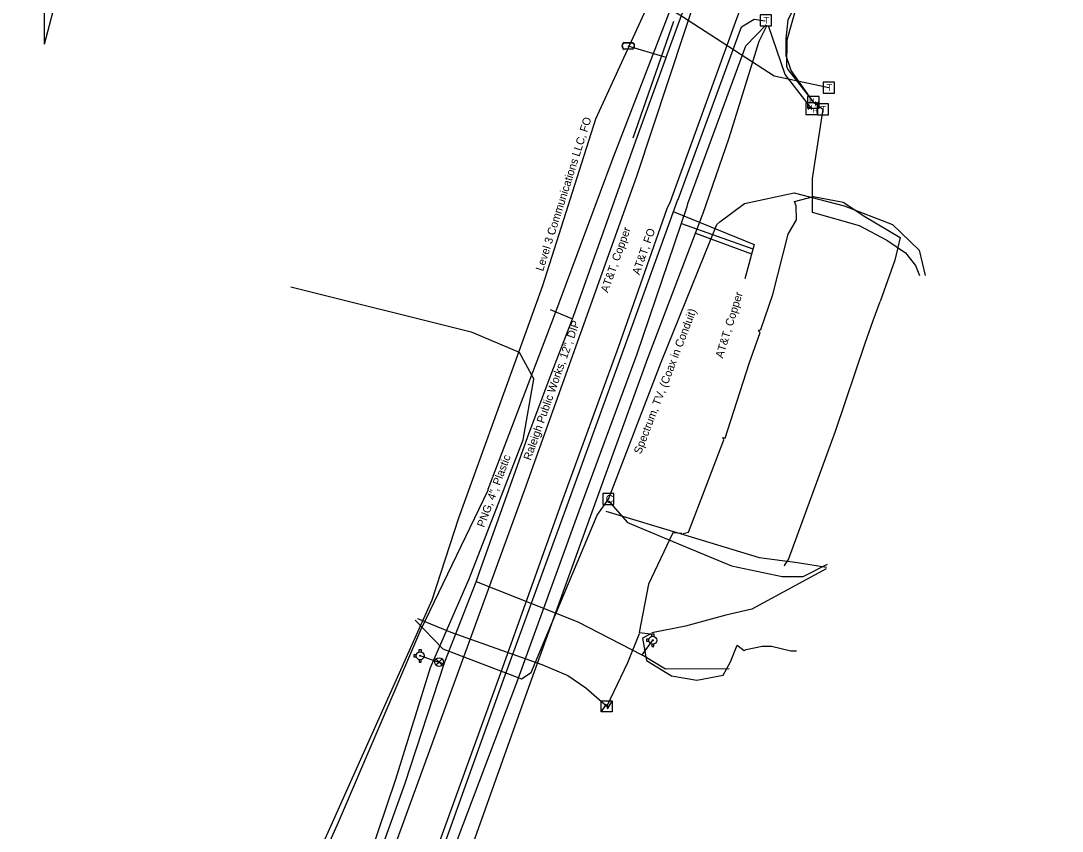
# Model space of a CAD drawing. Extents: x 2070721 to 2083039, y 729290 to 737883.
# Drawn here: x 2080924 to 2081444, y 733253 to 733658 of the extents above; entities that cross this region are included whole.
import ezdxf

# ---------------------------------------------------------------- set-up
doc = ezdxf.new("R2010")
doc.units = 0
for name, color, linetype in [('Cogo Default Point CELL', 7, 'Continuous'), ('COGO Default Point Elevation', 7, 'Continuous'), ('COGO Default Point Number', 7, 'Continuous'), ('Exist Utilities Gas UG Line SUE Cogo Point CELL', 7, 'Continuous'), ('Exist Utilities Gas UG Line SUE LOS B Cogo Comment', 7, 'Continuous'), ('Exist Utilities Gas Valve Cogo Elevation', 7, 'Continuous'), ('Exist Utilities Telephone UG Cable SUE LOS C Cogo Comment', 7, 'Continuous'), ('Exist Utilities Telephone UG Cable SUE LOS C Cogo Number', 7, 'Continuous'), ('Exist Utilities Telephone UG FO Cogo Point CELL', 7, 'Continuous'), ('Exist Utilities Telephone UG FO SUE LOS B Cogo Comment', 7, 'Continuous'), ('Exist Utilities Telephone UG FO SUE LOS B Cogo Number', 7, 'Continuous'), ('Exist Utilities TV Pedestal Cogo Elevation', 7, 'Continuous'), ('Exist Utilities TV Pedestal Cogo Number', 7, 'Continuous'), ('Exist Utilities TV UG Cable Cogo Point CELL', 7, 'Continuous'), ('Exist Utilities TV UG Cable SUE LOS C Cogo Comment', 7, 'Continuous'), ('Exist Utilities TV UG Cable SUE LOS C Cogo Number', 7, 'Continuous'), ('Exist Utilities TV UG Cable SUE LOS C Cogo Point CELL', 7, 'Continuous'), ('Exist Utilities Water Manhole Cogo Number', 7, 'Continuous'), ('Exist Utilities Water Meter Cogo Elevation', 7, 'Continuous'), ('Exist Utilities Water Meter Cogo Number', 7, 'Continuous')]:
    doc.layers.add(name, color=color, linetype=linetype)

msp = doc.modelspace()

# ---------------------------------------------------------------- linework, layer by layer
at = {"layer": 'Cogo Default Point CELL'}
msp.add_line((2081217.67, 733419.02), (2081217.67, 733419.02), dxfattribs=at)
msp.add_lwpolyline([(2081214.9, 733416.24), (2081220.45, 733416.24), (2081220.45, 733421.79), (2081214.9, 733421.79), (2081214.9, 733416.24)], dxfattribs=at)
at = {"layer": 'COGO Default Point Elevation'}
msp.add_lwpolyline([(2081134.76, 733339.06), (2081131.61, 733335.91), (2081133.18, 733337.48), (2081134.76, 733335.91), (2081131.61, 733339.06)], dxfattribs=at)
msp.add_circle((2081133.18, 733337.48), 2.23, dxfattribs=at)
at = {"layer": 'COGO Default Point Number'}
for p, q in [((2081239.93, 733348.42), (2081239.93, 733348.42)), ((2081123.71, 733340.65), (2081123.71, 733340.65))]:
    msp.add_line(p, q, dxfattribs=at)
for points in [[(2081238.01, 733348.93), (2081236.73, 733348.93), (2081236.73, 733347.91), (2081238.01, 733347.91)], [(2081239.41, 733350.33), (2081239.41, 733351.62), (2081240.44, 733351.62), (2081240.44, 733350.31)], [(2081123.2, 733342.57), (2081123.2, 733343.85), (2081124.22, 733343.85), (2081124.22, 733342.54)], [(2081239.41, 733346.51), (2081239.41, 733345.22), (2081240.44, 733345.22), (2081240.44, 733346.53)], [(2081121.8, 733341.17), (2081120.51, 733341.17), (2081120.51, 733340.14), (2081121.8, 733340.14)], [(2081123.2, 733338.74), (2081123.2, 733337.45), (2081124.22, 733337.45), (2081124.22, 733338.77)]]:
    msp.add_lwpolyline(points, dxfattribs=at)
for centre, radius in [((2081239.93, 733348.42), 1.98), ((2081239.93, 733348.42), 0.243), ((2081123.71, 733340.65), 1.98), ((2081123.71, 733340.65), 0.243)]:
    msp.add_circle(centre, radius, dxfattribs=at)
at = {"layer": 'Exist Utilities Gas Valve Cogo Elevation'}
for p, q in [((2081254.27, 733556.72), (2081289.92, 733543.99)), ((2081261.33, 733551.91), (2081289.31, 733541.49))]:
    msp.add_line(p, q, dxfattribs=at)
msp.add_lwpolyline([(2081250.19, 733562.64), (2081290.57, 733546.24), (2081285.89, 733528.96)], dxfattribs=at)
at = {"layer": 'Exist Utilities Telephone UG Cable SUE LOS C Cogo Comment'}
msp.add_line((2081230.17, 733599.51), (2081250.4, 733657.7), dxfattribs=at)
at = {"layer": 'Exist Utilities Telephone UG Cable SUE LOS C Cogo Number'}
msp.add_line((2081216.97, 733315.56), (2081216.97, 733315.56), dxfattribs=at)
msp.add_lwpolyline([(2081214.13, 733318.17), (2081219.68, 733318.17), (2081219.68, 733312.62), (2081214.13, 733312.62)], close=True, dxfattribs=at)
for points in [[(2081214.13, 733312.62), (2081216.77, 733316.56), (2081217.4, 733314.35), (2081219.68, 733318.17)], [(2081214.2, 733312.62), (2081216.77, 733316.35), (2081217.36, 733314.17), (2081219.68, 733318.02)]]:
    msp.add_lwpolyline(points, dxfattribs=at)
at = {"layer": 'Exist Utilities Telephone UG FO Cogo Point CELL'}
msp.add_line((2081227.69, 733645.4), (2081227.69, 733645.4), dxfattribs=at)
for points in [[(2081225.66, 733647.1), (2081229.73, 733647.1)], [(2081225.66, 733646.96), (2081229.73, 733646.96)], [(2081229.73, 733643.83), (2081225.63, 733643.83)], [(2081229.73, 733643.7), (2081225.63, 733643.7)]]:
    msp.add_lwpolyline(points, dxfattribs=at)
for centre, radius, start, end in [((2081226.39, 733645.39), 1.86, 113.178, 245.9794), ((2081226.4, 733645.39), 1.73, 115.3009, 243.7824), ((2081228.99, 733645.4), 1.86, 293.6483, 66.3084), ((2081229, 733645.4), 1.73, 295.1272, 64.8728)]:
    msp.add_arc(centre, radius, start, end, dxfattribs=at)
at = {"layer": 'Exist Utilities Telephone UG FO SUE LOS B Cogo Comment'}
for p, q in [((2081327.86, 733624.57), (2081327.86, 733624.57)), ((2081324.91, 733613.72), (2081324.91, 733613.72))]:
    msp.add_line(p, q, dxfattribs=at)
for points in [[(2081293.66, 733655.37), (2081299.26, 733655.37), (2081299.26, 733660.97), (2081293.66, 733660.97), (2081293.66, 733655.37)], [(2081325.14, 733621.74), (2081330.73, 733621.74), (2081330.73, 733627.34), (2081325.14, 733627.34), (2081325.14, 733621.74)], [(2081322.18, 733610.89), (2081327.78, 733610.89), (2081327.78, 733616.48), (2081322.18, 733616.48), (2081322.18, 733610.89)]]:
    msp.add_lwpolyline(points, dxfattribs=at)
at = {"layer": 'Exist Utilities Telephone UG FO SUE LOS B Cogo Number'}
for p, q in [((2081317.3, 733620.09), (2081317.3, 733614.36)), ((2081323.03, 733620.09), (2081317.3, 733620.09)), ((2081323.03, 733614.36), (2081323.03, 733620.09)), ((2081316.47, 733616.9), (2081316.47, 733611.18)), ((2081322.19, 733616.9), (2081316.47, 733616.9)), ((2081317.3, 733614.36), (2081323.03, 733614.36)), ((2081319.33, 733614.04), (2081319.33, 733614.04)), ((2081320.17, 733617.22), (2081320.17, 733617.22)), ((2081322.19, 733611.18), (2081322.19, 733616.9)), ((2081316.47, 733611.18), (2081322.19, 733611.18))]:
    msp.add_line(p, q, dxfattribs=at)
at = {"layer": 'Exist Utilities TV Pedestal Cogo Elevation'}
msp.add_line((2081202.55, 733357.67), (2081234.51, 733341.1), dxfattribs=at)
for points in [[(2081246.63, 733639.55), (2081247.18, 733641.17), (2081265.29, 733690.74)], [(2081246.63, 733639.55), (2081245.38, 733639.93), (2081227.6, 733645.35)], [(2081199.8, 733508.96), (2081200.26, 733510.4), (2081231.43, 733598.04), (2081246.63, 733639.55)], [(2081199.8, 733508.96), (2081199.23, 733509.2), (2081188.89, 733513.59)], [(2081151.65, 733377.59), (2081153.29, 733382.5), (2081177.58, 733450.17), (2081188.69, 733479.97), (2081199.8, 733508.96)], [(2081135.71, 733336.57), (2081136.04, 733337.71), (2081151.65, 733377.59)], [(2081151.69, 733377.7), (2081151.69, 733377.7), (2081202.55, 733357.67)], [(2081234.51, 733341.1), (2081235.06, 733341.83), (2081240, 733348.4)], [(2081135.71, 733336.57), (2081133.78, 733337.11), (2081133.21, 733337.3), (2081123.72, 733340.66)], [(2081278.15, 733334.18), (2081246.21, 733333.89), (2081234.51, 733341.1)], [(2080968.02, 732853.09), (2080971.09, 732863.55), (2080973.36, 732870.49), (2081004.03, 732959.14), (2081024.87, 733018.36), (2081055.27, 733107.45), (2081086.77, 733195.01), (2081116.19, 733277.07), (2081135.71, 733336.57)]]:
    msp.add_lwpolyline(points, dxfattribs=at)
at = {"layer": 'Exist Utilities TV Pedestal Cogo Number'}
for points in [[(2081157.6, 733423.49), (2081157.75, 733423.93), (2081190.43, 733509.93), (2081219.7, 733588.19), (2081252.91, 733674.58), (2081286.02, 733770.88), (2081302.57, 733820.59), (2081312.47, 733846.89)], [(2080924.17, 732884.04), (2080930.33, 732882.17), (2080949.02, 732923.62), (2080986.84, 733002.49), (2081018.88, 733098.52), (2081046.79, 733177.28), (2081082.41, 733256.43), (2081124.09, 733353.56), (2081157.6, 733423.49)]]:
    msp.add_lwpolyline(points, dxfattribs=at)
at = {"layer": 'Exist Utilities TV UG Cable Cogo Point CELL'}
for points in [[(2080953.21, 732796.69), (2081054.09, 733077.62), (2081111.09, 733245.57), (2081176.08, 733423.78), (2081231.97, 733580.28), (2081320.16, 733847.08), (2081418.84, 734093.09), (2081467.34, 734224.03), (2081494.06, 734287.2), (2081526.74, 734352.01), (2081556, 734404.62), (2081808.13, 734757.73), (2081845.73, 734804.26), (2081874.67, 734821.58), (2081898.66, 734810.94), (2081917.15, 734795.51)], [(2080936, 733646.3), (2080936, 733671.46), (2080936, 733693.97), (2080950.03, 733706.27), (2081027.4, 733703.51), (2081032.1, 733693.76)], [(2080936, 733646.3), (2080942.8, 733672.51), (2080942.8, 733689.3), (2080954.18, 733700.25), (2080971.23, 733703.78), (2081003.67, 733703.78), (2081018.65, 733703.13), (2081031.75, 733693.2)], [(2081236.04, 733672.01), (2081254.79, 733660.17), (2081300.55, 733630.39), (2081327.86, 733624.58)], [(2081252.65, 733568.73), (2081284.23, 733654.98), (2081290.61, 733658.83), (2081296.02, 733657.99)], [(2081257.51, 733566.68), (2081286.37, 733645.5), (2081296.64, 733655.96)], [(2081264.77, 733561.01), (2081264.9, 733561.27), (2081278.02, 733599.54), (2081293.06, 733647.81), (2081297.01, 733655.83)], [(2081324.91, 733613.72), (2081319.52, 733579.11), (2081319.52, 733562.34), (2081343.1, 733555.71), (2081356.84, 733548.33), (2081366.23, 733541.95), (2081371.13, 733535.72), (2081373.21, 733530.68)], [(2080971.45, 732791.05), (2081028.93, 732955.93), (2081037.58, 732965.12), (2081059.34, 733032.5), (2081099.5, 733145.5), (2081127.24, 733222.27), (2081165.53, 733329.08), (2081197.08, 733415.76), (2081225.51, 733493.81), (2081252.34, 733568.18), (2081252.65, 733568.73)], [(2080977.85, 732787.5), (2081009.55, 732879.6), (2081045.87, 732978.13), (2081063.56, 733030.35), (2081103.18, 733143.81), (2081131.57, 733220.23), (2081172.06, 733327.38), (2081203.1, 733413.05), (2081232.13, 733491.49), (2081257.07, 733565.11), (2081257.51, 733566.68)], [(2080980.31, 732787.04), (2081017.13, 732880.26), (2081044.65, 732962.53), (2081058.02, 732999.54), (2081069.26, 733036.84), (2081073.31, 733048.09), (2081079.75, 733057.99), (2081085.51, 733069.49), (2081110.84, 733140.06), (2081139.9, 733217.95), (2081177.19, 733322.59), (2081208.97, 733410.75), (2081237.5, 733489.4), (2081264.77, 733561.01)], [(2081059.04, 733525.1), (2081149.16, 733502.55), (2081173.19, 733492.4), (2081180.53, 733478.86)], [(2080944.31, 732798.44), (2080951.65, 732814.71), (2080971.81, 732874.01), (2081001.7, 732960.05), (2081020.52, 733019.4), (2081051.78, 733107.87), (2081085.75, 733202.6), (2081111.57, 733279.04), (2081128.94, 733334.77), (2081148.26, 733379.04), (2081175.1, 733448.52), (2081180.53, 733478.86)]]:
    msp.add_lwpolyline(points, dxfattribs=at)
at = {"layer": 'Exist Utilities TV UG Cable SUE LOS C Cogo Comment'}
for points in [[(2081255.08, 733401.83), (2081257.7, 733402.5), (2081266.54, 733425.38), (2081275.48, 733448.49), (2081274.96, 733449.76), (2081276.11, 733449.4), (2081280.42, 733462.89), (2081288.23, 733487.19), (2081293.53, 733502.2), (2081292.78, 733503.17), (2081293.98, 733503.64), (2081299.88, 733521.18), (2081307.63, 733551.29), (2081311.78, 733558.44), (2081311.53, 733565.53), (2081310.75, 733567.69), (2081320.22, 733570.19), (2081335.06, 733567.36), (2081345.85, 733560.11), (2081363.58, 733549.71), (2081360.92, 733538.3), (2081353.48, 733517.62)], [(2081305.65, 733385.58), (2081305.68, 733385.74), (2081307.72, 733388.7), (2081331.3, 733452.95), (2081346.05, 733496.93), (2081350.09, 733508.16), (2081353.48, 733517.62)], [(2081216.46, 733412.89), (2081255.27, 733401.21), (2081293.04, 733389.74), (2081312.23, 733387.32), (2081326.7, 733384.87)], [(2081254.52, 733401.71), (2081249.97, 733402.02), (2081237.71, 733376.5), (2081233.12, 733352.36), (2081238.98, 733351.69), (2081234.79, 733349.44), (2081236.79, 733338.35), (2081249.32, 733330.71), (2081262.01, 733328.39), (2081275.02, 733331.05), (2081278.71, 733337.68), (2081282.09, 733345.97), (2081285.66, 733343.35), (2081286.57, 733343.74), (2081294.52, 733345.49), (2081299.28, 733345.49), (2081308.93, 733343.11), (2081311.71, 733343.11)], [(2081326.62, 733384.18), (2081289.46, 733364.01), (2081276.44, 733360.9), (2081256.28, 733355.4), (2081239.4, 733352.05)], [(2081122.35, 733359.34), (2081139.09, 733352.49), (2081184.49, 733336.32), (2081197.51, 733330.86), (2081206.4, 733324.71), (2081216.97, 733315.56)], [(2081233.19, 733351.65), (2081227.37, 733337.09), (2081216.98, 733315.54)]]:
    msp.add_lwpolyline(points, dxfattribs=at)
at = {"layer": 'Exist Utilities TV UG Cable SUE LOS C Cogo Number'}
for points in [[(2081271.85, 733556.1), (2081273.4, 733557.42), (2081285.71, 733566.63), (2081310.55, 733571.95), (2081335.49, 733565.44), (2081359.75, 733556.12), (2081373.01, 733543.42), (2081376.11, 733530.71)], [(2081121.25, 733358.53), (2081135.11, 733344.16), (2081174.32, 733329.18), (2081179.16, 733332.24), (2081212.15, 733410.86), (2081217.78, 733418.98), (2081244.16, 733487.45), (2081271.85, 733556.1)], [(2081217.8, 733418.14), (2081227.38, 733407.32), (2081256.72, 733394.96), (2081279.22, 733385.68), (2081304.54, 733380.27), (2081315.06, 733380.27), (2081327.24, 733386.44)]]:
    msp.add_lwpolyline(points, dxfattribs=at)
at = {"layer": 'Exist Utilities TV UG Cable SUE LOS C Cogo Point CELL'}
for points in [[(2081248.81, 733567.64), (2081281.2, 733657.22), (2081333.49, 733797.21), (2081369.06, 733900.16), (2081403.11, 733993), (2081427.18, 734053.08), (2081460.75, 734136.42), (2081485.85, 734201.8), (2081501.51, 734239.63), (2081538.45, 734313.8), (2081542.88, 734322.62)], [(2081306.87, 733635.01), (2081307.14, 733648.47), (2081313.93, 733672.81), (2081326.66, 733686.61), (2081341.59, 733681.48), (2081372.31, 733676.73), (2081416.7, 733673.36), (2081432.98, 733673.8)], [(2081320.17, 733617.22), (2081309.01, 733633.17), (2081306.6, 733640.45), (2081306.6, 733648.93), (2081307.64, 733658.5), (2081314.26, 733672.29), (2081326.97, 733686.41), (2081341.67, 733682.07), (2081372.57, 733676.97), (2081416.57, 733673.92), (2081433.13, 733674.23)], [(2081060.57, 733214.24), (2081129.62, 733368.62), (2081142.99, 733409.6), (2081173.13, 733492.79), (2081185.02, 733525.68), (2081211.4, 733608.97), (2081237.57, 733665.91), (2081235.81, 733672.2)], [(2081319.38, 733613.95), (2081306.04, 733631.11), (2081297.82, 733655.43)], [(2081306.87, 733635.01), (2081307.41, 733633.56), (2081320.02, 733617.47), (2081324.92, 733613.79)], [(2080974.54, 732788.58), (2081004.48, 732877.32), (2081038.77, 732975.1), (2081057.5, 733033.86), (2081097.09, 733146.25), (2081124.3, 733222.73), (2081163.35, 733330.31), (2081194.31, 733416.96), (2081222.79, 733494.92), (2081247.13, 733564.12), (2081248.81, 733567.64)]]:
    msp.add_lwpolyline(points, dxfattribs=at)

# ---------------------------------------------------------------- texts
at = {"layer": 'Cogo Default Point CELL'}
msp.add_text('C', height=4, dxfattribs=at).set_placement((2081216.37, 733417.02))
at = {"layer": 'Exist Utilities Gas UG Line SUE Cogo Point CELL'}
msp.add_text('Raleigh Public Works, 12", DIP', height=4, rotation=70.4185, dxfattribs=at).set_placement((2081178.91, 733438.03))
at = {"layer": 'Exist Utilities Gas UG Line SUE LOS B Cogo Comment'}
for s, rotation, p in [('Level 3 Communications LLC, FO', 72.4199, (2081185.1, 733532.57)), ('AT&T, FO', 70.6203, (2081233.26, 733530.7))]:
    msp.add_text(s, height=4, rotation=rotation, dxfattribs=at).set_placement(p)
at = {"layer": 'Exist Utilities Telephone UG FO SUE LOS B Cogo Comment'}
for p in [(2081295.26, 733656.49), (2081326.73, 733622.86), (2081323.78, 733612)]:
    msp.add_text('T', height=3.42, dxfattribs=at).set_placement(p)
at = {"layer": 'Exist Utilities Telephone UG FO SUE LOS B Cogo Number'}
for p in [(2081318.08, 733616.63), (2081317.25, 733613.45), (2081319.82, 733611.98), (2081320.65, 733615.17)]:
    msp.add_text('H', height=2.5, dxfattribs=at).set_placement(p)
at = {"layer": 'Exist Utilities Water Manhole Cogo Number'}
msp.add_text('Spectrum, TV, (Coax in Conduit) ', height=4, rotation=68.9276, dxfattribs=at).set_placement((2081233.99, 733441.12))
at = {"layer": 'Exist Utilities Water Meter Cogo Elevation'}
msp.add_text('PNG, 4", Plastic', height=4, rotation=69.4935, dxfattribs=at).set_placement((2081155.66, 733404.49))
at = {"layer": 'Exist Utilities Water Meter Cogo Number'}
for rotation, p in [(70.3476, (2081217.47, 733521.84)), (72.9166, (2081274.9, 733489.07))]:
    msp.add_text('AT&T, Copper', height=4, rotation=rotation, dxfattribs=at).set_placement(p)

doc.saveas('drawing.dxf')
